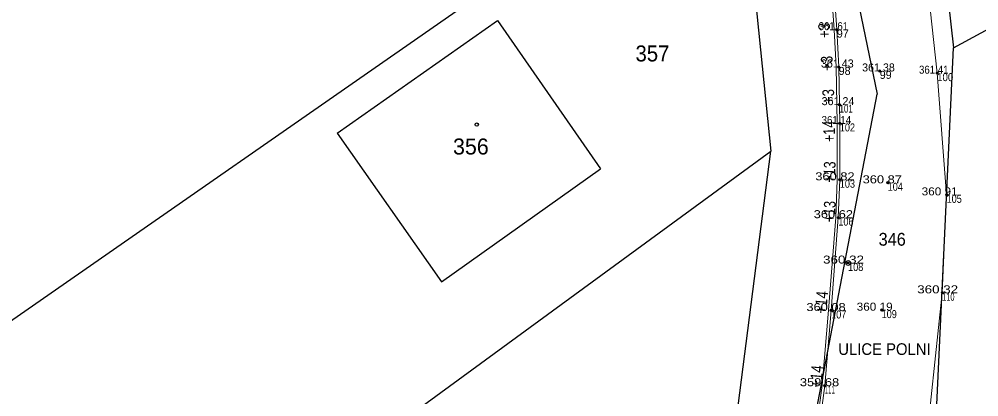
# Model space of a CAD drawing. Extents: x -592965 to -592390, y -1145071 to -1144631.
# Drawn here: x -592689.4 to -592638.4, y -1144900.5 to -1144880.5 of the extents above; entities that cross this region are included whole.
import ezdxf
from ezdxf.enums import TextEntityAlignment as Align

# ---------------------------------------------------------------- set-up
doc = ezdxf.new("R2010")
doc.units = 0
doc.header["$LTSCALE"] = 0.17
doc.header["$PDMODE"] = 32
doc.header["$PDSIZE"] = 0.085
for name, color, linetype, lineweight in [('1', 7, 'Continuous', 13), ('3', 7, 'Continuous', 13), ('4', 7, 'Continuous', 25)]:
    doc.layers.add(name, color=color, linetype=linetype, lineweight=lineweight)
doc.layers.add('2', color=7, linetype='Continuous')

msp = doc.modelspace()

# ---------------------------------------------------------------- linework, layer by layer
at = {"layer": '1'}
for p, q in [((-592645.98, -1144881.05), (-592646.12, -1144881.06)), ((-592645.84, -1144885.03), (-592645.98, -1144885.03)), ((-592645.82, -1144886.03), (-592645.96, -1144886.03))]:
    msp.add_line(p, q, dxfattribs=at)
for points in [[(-592641.79, -1144908.72), (-592641.16, -1144902.38), (-592640.38, -1144895.02), (-592640.15, -1144889.82), (-592640.65, -1144883.36), (-592641.29, -1144877.49), (-592642.3, -1144871.74), (-592643.21, -1144867.79), (-592644.53, -1144861.22), (-592645.89, -1144855.01), (-592647.22, -1144849.42), (-592648.49, -1144841.98), (-592649.04, -1144837.88), (-592648.65, -1144833.94), (-592647.63, -1144830.74), (-592645.94, -1144827.26), (-592642.72, -1144822.58), (-592638.67, -1144817.55), (-592634.67, -1144812.8), (-592632.14, -1144809.3), (-592630.54, -1144806.22), (-592629.58, -1144805.74)], [(-592647.47, -1144872.18), (-592646.45, -1144878.08), (-592646.19, -1144880.05), (-592646.12, -1144881.06), (-592646.02, -1144883.03), (-592645.98, -1144885.03), (-592645.96, -1144886.03), (-592645.96, -1144889.02), (-592646.04, -1144891.02), (-592646.42, -1144895.95), (-592646.76, -1144899.93), (-592647.02, -1144901.9)], [(-592647.33, -1144872.14), (-592646.31, -1144878.06), (-592646.05, -1144880.04), (-592645.98, -1144881.05), (-592645.88, -1144883.03), (-592645.84, -1144885.03), (-592645.82, -1144886.03), (-592645.82, -1144889.02), (-592645.9, -1144891.03), (-592646.28, -1144895.96), (-592646.62, -1144899.95), (-592646.88, -1144901.92)]]:
    msp.add_lwpolyline(points, dxfattribs=at)
msp.add_circle((-592645.38, -1144893.44), 0.125, dxfattribs=at)
at = {"layer": '2'}
for p in [(-592645.98, -1144881.05), (-592645.88, -1144883.03), (-592643.7, -1144883.24), (-592640.65, -1144883.36), (-592645.84, -1144885.03), (-592645.82, -1144886.03), (-592645.82, -1144889.02), (-592643.28, -1144889.18), (-592640.15, -1144889.82), (-592645.9, -1144891.03), (-592645.38, -1144893.44), (-592640.38, -1144895.02), (-592646.28, -1144895.96), (-592643.6, -1144895.94), (-592646.62, -1144899.95)]:
    msp.add_point(p, dxfattribs=at)
at = {"layer": '3'}
for centre, radius in [((-592645.9801, -1144881.0499), 0.0625), ((-592645.9801, -1144881.0499), 0.0395), ((-592645.9801, -1144881.0499), 0.0125), ((-592645.8801, -1144883.0299), 0.0625), ((-592645.8801, -1144883.0299), 0.0395), ((-592645.8801, -1144883.0299), 0.0125), ((-592643.7001, -1144883.2399), 0.0625), ((-592643.7001, -1144883.2399), 0.0395), ((-592643.7001, -1144883.2399), 0.0125), ((-592640.6501, -1144883.3599), 0.0625), ((-592640.6501, -1144883.3599), 0.0395), ((-592640.6501, -1144883.3599), 0.0125), ((-592645.8401, -1144885.0299), 0.0625), ((-592645.8401, -1144885.0299), 0.0395), ((-592645.8401, -1144885.0299), 0.0125), ((-592645.8201, -1144886.0299), 0.0625), ((-592645.8201, -1144886.0299), 0.0395), ((-592645.8201, -1144886.0299), 0.0125), ((-592645.8201, -1144889.0199), 0.0625), ((-592645.8201, -1144889.0199), 0.0395), ((-592645.8201, -1144889.0199), 0.0125), ((-592643.2801, -1144889.1799), 0.0625), ((-592643.2801, -1144889.1799), 0.0395), ((-592643.2801, -1144889.1799), 0.0125), ((-592640.1501, -1144889.8199), 0.0625), ((-592640.1501, -1144889.8199), 0.0395), ((-592640.1501, -1144889.8199), 0.0125), ((-592645.9001, -1144891.0299), 0.0625), ((-592645.9001, -1144891.0299), 0.0395), ((-592645.9001, -1144891.0299), 0.0125), ((-592645.3801, -1144893.4399), 0.0625), ((-592645.3801, -1144893.4399), 0.0395), ((-592645.3801, -1144893.4399), 0.0125), ((-592640.3801, -1144895.0199), 0.0625), ((-592640.3801, -1144895.0199), 0.0395), ((-592640.3801, -1144895.0199), 0.0125), ((-592646.2801, -1144895.9599), 0.0625), ((-592646.2801, -1144895.9599), 0.0395), ((-592646.2801, -1144895.9599), 0.0125), ((-592643.6001, -1144895.9399), 0.0625), ((-592643.6001, -1144895.9399), 0.0395), ((-592643.6001, -1144895.9399), 0.0125), ((-592646.6201, -1144899.9499), 0.0625), ((-592646.6201, -1144899.9499), 0.0395), ((-592646.6201, -1144899.9499), 0.0125)]:
    msp.add_circle(centre, radius, dxfattribs=at)
at = {"layer": '4'}
for p, q in [((-592652.44, -1144842.96), (-592643.83, -1144884.47)), ((-592641.99, -1144862.15), (-592639.79, -1144882.02)), ((-592691.98, -1144897.99), (-592651.29, -1144869.7)), ((-592651.29, -1144869.7), (-592649.48, -1144887.5)), ((-592639.79, -1144882.02), (-592635.02, -1144879.44)), ((-592672.51, -1144886.55), (-592664, -1144880.56)), ((-592664, -1144880.56), (-592658.52, -1144888.44)), ((-592641.03, -1144908.63), (-592639.79, -1144882.02)), ((-592650.24, -1144917.82), (-592643.83, -1144884.47)), ((-592672.51, -1144886.55), (-592666.97, -1144894.43)), ((-592687.76, -1144915.48), (-592649.48, -1144887.5)), ((-592651.93, -1144906.46), (-592649.48, -1144887.5)), ((-592666.97, -1144894.43), (-592658.52, -1144888.44))]:
    msp.add_line(p, q, dxfattribs=at)
msp.add_circle((-592665.1, -1144886.09), 0.0875, dxfattribs=at)

# ---------------------------------------------------------------- texts
at = {"layer": '1'}
for s, rotation, width, p in [('+3', 91.146, 0.85, (-592646.3403, -1144881.0872)), ('+3', 91.146, 0.85, (-592646.2003, -1144882.8372)), ('+3', 91.146, 0.85, (-592646.1203, -1144884.5972)), ('+14', 91.146, 0.8, (-592646.0805, -1144886.4477)), ('+13', 87.709, 0.8, (-592646.0597, -1144888.6199)), ('+13', 87.709, 0.8, (-592646.0597, -1144890.7199)), ('+14', 85.117, 0.85, (-592646.4891, -1144895.5494)), ('+14', 85.117, 0.85, (-592646.7491, -1144899.4894))]:
    msp.add_text(s, height=0.62, rotation=rotation, dxfattribs=dict(at, width=width)).set_placement(p, align=Align.CENTER)
at = {"layer": '1', "width": 0.95}
msp.add_text('ULICE POLNI', height=0.62, dxfattribs=at).set_placement((-592643.45, -1144898.32), align=Align.CENTER)
at = {"layer": '2'}
for s, p in [('97', (-592645.98, -1144881.475)), ('98', (-592645.88, -1144883.455)), ('99', (-592643.7, -1144883.665))]:
    msp.add_text(s, height=0.425, dxfattribs=at).set_placement(p)
for s, width, p in [('100', 0.9, (-592640.65, -1144883.785)), ('101', 0.75, (-592645.84, -1144885.455)), ('102', 0.85, (-592645.82, -1144886.455)), ('103', 0.85, (-592645.82, -1144889.445)), ('104', 0.85, (-592643.28, -1144889.605)), ('105', 0.85, (-592640.15, -1144890.245)), ('106', 0.85, (-592645.9, -1144891.455)), ('108', 0.85, (-592645.38, -1144893.865)), ('110', 0.6, (-592640.38, -1144895.445)), ('107', 0.85, (-592646.28, -1144896.385)), ('109', 0.85, (-592643.6, -1144896.365)), ('111', 0.45, (-592646.62, -1144900.375))]:
    msp.add_text(s, height=0.425, dxfattribs=dict(at, width=width)).set_placement(p)
at = {"layer": '3'}
for s, width, p in [('361 61', 0.9, (-592646.1625, -1144881.08)), ('361 41', 0.9, (-592640.8325, -1144883.39)), ('361 14', 0.9, (-592646.0025, -1144886.06)), ('360 82', 1.2, (-592646.078, -1144889.05)), ('360 87', 1.2, (-592643.5665, -1144889.21)), ('360 91', 1.1, (-592640.52, -1144889.85)), ('360 62', 1.2, (-592646.1645, -1144891.06)), ('360 32', 1.25, (-592645.623, -1144893.47)), ('360 32', 1.25, (-592640.623, -1144895.05)), ('360 08', 1.2, (-592646.5515, -1144895.99)), ('360 19', 1.1, (-592643.97, -1144895.97)), ('359 68', 1.2, (-592646.897, -1144899.98))]:
    msp.add_text(s, height=0.425, dxfattribs=dict(at, width=width)).set_placement(p, align=Align.CENTER)
for s, p in [('361 43', (-592645.9535, -1144883.06)), ('361 38', (-592643.7685, -1144883.27)), ('361 24', (-592645.917, -1144885.06))]:
    msp.add_text(s, height=0.425, dxfattribs=at).set_placement(p, align=Align.CENTER)
at = {"layer": '4', "width": 0.95}
for s, height, p in [('357', 0.85, (-592656.67, -1144882.74)), ('346', 0.68, (-592643.76, -1144892.52))]:
    msp.add_text(s, height=height, dxfattribs=at).set_placement(p)
at = {"layer": '4'}
msp.add_text('356', height=0.85, dxfattribs=at).set_placement((-592666.36, -1144887.68))

doc.saveas('drawing.dxf')
